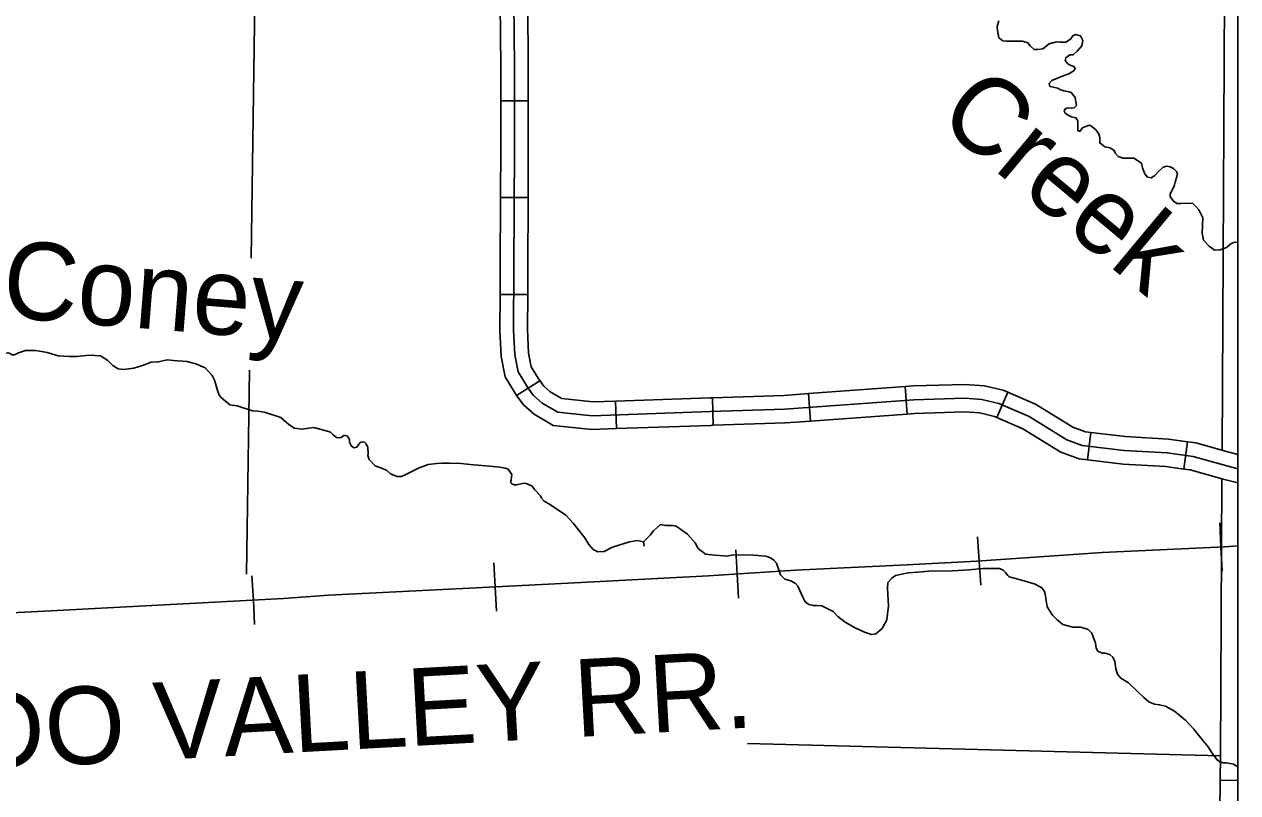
# Model space of a CAD drawing. Extents: x 8749 to 11879, y 13275 to 15339.
# Drawn here: x 10827.5 to 10959.7, y 14275.3 to 14359.1 of the extents above; entities that cross this region are included whole.
import ezdxf

# ---------------------------------------------------------------- set-up
doc = ezdxf.new("R2010")
doc.units = 0
for name, color, linetype in [('Level 31', 7, 'Continuous'), ('Level 32', 7, 'Continuous'), ('Level 35', 7, 'Continuous'), ('Level 4', 7, 'Continuous'), ('Level 40', 7, 'Continuous'), ('Level 5', 7, 'Continuous'), ('R_Draft', 7, 'Continuous')]:
    doc.layers.add(name, color=color, linetype=linetype)

msp = doc.modelspace()

# ---------------------------------------------------------------- linework, layer by layer
at = {"layer": 'Level 31'}
for points in [[(10881.44, 14382.4), (10881.09, 14375.29), (10880.86, 14361.44), (10880.91, 14354.46), (10880.91, 14345.65)], [(10880.91, 14345.65), (10880.86, 14332.43), (10880.82, 14325.76), (10880.95, 14323.05), (10881.31, 14321.18), (10882.42, 14319.41), (10883, 14318.6), (10883.93, 14317.78), (10885.62, 14316.8), (10889.39, 14316.4), (10902.27, 14316.85), (10910.36, 14317.12), (10924.44, 14318.14), (10929.99, 14318.32), (10931.85, 14318.18), (10933.67, 14317.74), (10937.01, 14316.32), (10941.09, 14313.78), (10942.78, 14313.16), (10947.35, 14312.62), (10952.02, 14312.36), (10954.86, 14311.96), (10958.52, 14310.93), (10959.72, 14310.62)], [(10923.65, 14300.13), (10931.3, 14300.54), (10944.95, 14301.48), (10958.32, 14302.12), (10959.72, 14302.2)], [(10745.11, 14290.62), (10758.52, 14291.3), (10770.32, 14291.88), (10786.12, 14292.74), (10797.56, 14293.42), (10807.72, 14293.91), (10816.51, 14294.45), (10829.7, 14295.08), (10847.57, 14296.03), (10855.76, 14296.48), (10860.67, 14296.84), (10876.02, 14297.61), (10886.78, 14298.15), (10902.05, 14298.96), (10911.55, 14299.55), (10923.65, 14300.13)]]:
    msp.add_lwpolyline(points, dxfattribs=at)
at = {"layer": 'Level 32'}
for p, q in [((10879.41, 14350.73), (10882.41, 14350.73)), ((10879.39, 14340.18), (10882.39, 14340.17)), ((10879.35, 14329.62), (10882.35, 14329.6)), ((10881.15, 14318.61), (10883.69, 14320.2)), ((10923.71, 14316.58), (10923.5, 14319.57)), ((10902.57, 14315.36), (10902.48, 14318.36)), ((10913.18, 14315.82), (10912.96, 14318.81)), ((10933.48, 14316.19), (10934.66, 14318.95)), ((10892.02, 14314.99), (10891.92, 14317.99)), ((10943.36, 14311.58), (10943.71, 14314.56)), ((10953.83, 14310.59), (10954.25, 14313.56))]:
    msp.add_line(p, q, dxfattribs=at)
for points in [[(10879.37, 14361.28), (10879.41, 14354.45), (10879.41, 14350.73)], [(10882.36, 14361.3), (10882.41, 14354.46), (10882.41, 14350.73)], [(10879.41, 14350.73), (10879.41, 14345.66), (10879.39, 14340.18)], [(10882.41, 14350.73), (10882.41, 14345.65), (10882.39, 14340.17)], [(10879.39, 14340.18), (10879.36, 14332.44), (10879.35, 14329.62)], [(10882.39, 14340.17), (10882.36, 14332.42), (10882.35, 14329.6)], [(10879.35, 14329.62), (10879.32, 14325.73), (10879.46, 14322.87), (10879.89, 14320.63), (10881.15, 14318.61)], [(10882.35, 14329.6), (10882.32, 14325.79), (10882.45, 14323.23), (10882.73, 14321.74), (10883.69, 14320.2)], [(10883.67, 14320.24), (10884.11, 14319.62), (10884.81, 14319.01), (10886.09, 14318.26), (10889.45, 14317.91), (10891.92, 14317.99)], [(10912.96, 14318.81), (10923.5, 14319.57)], [(10923.5, 14319.57), (10924.36, 14319.64), (10930.02, 14319.82), (10932.09, 14319.67), (10934.15, 14319.17), (10934.66, 14318.95)], [(10881.14, 14318.62), (10881.17, 14318.57), (10881.88, 14317.59), (10883.05, 14316.56), (10885.14, 14315.35), (10889.34, 14314.9), (10892.02, 14314.99)], [(10891.92, 14317.99), (10902.22, 14318.35), (10902.48, 14318.36)], [(10902.48, 14318.36), (10910.28, 14318.61), (10912.96, 14318.81)], [(10934.66, 14318.95), (10937.7, 14317.65), (10941.75, 14315.14), (10943.13, 14314.63), (10943.71, 14314.56)], [(10923.71, 14316.58), (10924.51, 14316.64), (10929.96, 14316.81), (10931.62, 14316.7), (10933.2, 14316.31), (10933.48, 14316.19)], [(10902.57, 14315.36), (10910.44, 14315.62), (10913.18, 14315.82)], [(10913.18, 14315.82), (10923.71, 14316.58)], [(10933.48, 14316.19), (10936.31, 14314.98), (10940.43, 14312.43), (10942.43, 14311.69), (10943.36, 14311.58)], [(10892.02, 14314.99), (10902.32, 14315.35), (10902.57, 14315.36)], [(10943.71, 14314.56), (10947.48, 14314.12), (10952.17, 14313.85), (10954.25, 14313.56)], [(10954.25, 14313.56), (10955.17, 14313.43), (10958.91, 14312.38), (10959.72, 14312.17)], [(10943.36, 14311.58), (10947.23, 14311.13), (10951.87, 14310.86), (10953.83, 14310.59)], [(10953.83, 14310.59), (10954.55, 14310.49), (10958.13, 14309.48), (10959.72, 14309.08)]]:
    msp.add_lwpolyline(points, dxfattribs=at)
at = {"layer": 'Level 35'}
for points in [[(10934.13, 14357.26), (10933.7, 14357.6), (10933.55, 14358.38), (10933.5, 14358.81), (10933.7, 14359.44)], [(10941.78, 14355.75), (10942.21, 14356.12), (10942.72, 14356.73), (10942.84, 14357.31), (10942.57, 14357.79), (10942.04, 14357.94), (10941.76, 14357.81), (10941.48, 14357.43), (10941, 14357.11), (10940.32, 14357.13), (10939.97, 14357.16)], [(10939.97, 14357.16), (10939.19, 14356.95), (10938.49, 14356.4), (10937.93, 14356.3), (10937.53, 14356.32), (10937.12, 14356.73), (10936.85, 14357.06), (10936.27, 14357.23), (10935.11, 14357.21), (10934.55, 14357.21), (10934.13, 14357.26)], [(10940.12, 14352.1), (10939.29, 14352.3), (10939.22, 14352.4), (10939.17, 14352.62), (10939.47, 14352.95), (10940.7, 14353.46), (10941.31, 14353.66), (10941.91, 14354.04), (10942.01, 14354.26), (10941.86, 14354.47), (10941.46, 14354.62), (10941.21, 14354.77), (10940.9, 14355.12), (10940.98, 14355.42), (10941.41, 14355.73), (10941.78, 14355.75)], [(10941.6, 14348.98), (10941.16, 14349.2), (10940.9, 14349.38), (10940.8, 14349.6), (10940.88, 14349.8), (10941.16, 14349.96), (10941.61, 14349.91), (10941.89, 14349.96), (10942.16, 14350.23), (10942.01, 14351.07), (10941.58, 14351.62), (10941.21, 14351.75), (10940.78, 14351.82), (10940.35, 14351.97), (10940.12, 14352.1)], [(10949.24, 14343.92), (10948.4, 14344.47), (10947.62, 14344.49), (10947.25, 14344.49), (10946.69, 14344.64), (10946.41, 14344.97), (10946.26, 14345.32), (10945.83, 14345.6), (10945.23, 14345.7), (10944.68, 14346.13), (10944.7, 14346.71), (10944.6, 14347.14), (10944.22, 14347.59), (10943.67, 14348.02), (10943.42, 14348.05), (10942.81, 14347.77), (10942.53, 14347.39), (10942.28, 14347.49), (10942.31, 14348), (10942.31, 14348.53), (10942.08, 14348.88), (10941.6, 14348.98)], [(10957.8, 14334.47), (10957.2, 14334.46), (10956.59, 14334.89), (10955.99, 14335.54), (10955.86, 14336.3), (10955.91, 14337.96), (10955.48, 14338.85), (10955.18, 14339.18), (10954.83, 14339.53), (10954.05, 14339.58), (10953.54, 14339.53), (10953.09, 14339.53), (10952.69, 14339.83), (10952.36, 14340.31), (10952.34, 14340.59), (10952.56, 14340.97), (10952.81, 14341.44), (10952.84, 14341.57), (10952.91, 14341.87), (10953.14, 14342.73), (10953.04, 14343.03), (10952.71, 14343.34), (10952.34, 14343.54), (10951.98, 14343.59), (10951.58, 14343.49), (10951.1, 14343.03), (10950.67, 14342.58), (10950.27, 14342.33), (10949.89, 14342.4), (10949.59, 14342.76), (10949.34, 14343.41), (10949.24, 14343.92)], [(10957.8, 14334.47), (10958.48, 14334.75), (10959, 14335.18), (10959.41, 14335.31), (10959.72, 14335.29)], [(10839.45, 14321.58), (10838.29, 14321.43), (10837.74, 14321.5), (10837.14, 14321.86), (10836.61, 14322.41), (10835.8, 14322.92), (10834.62, 14322.99), (10833.26, 14322.87), (10832.42, 14322.87), (10831.19, 14322.94), (10829.98, 14323.29), (10828.75, 14323.52), (10827.64, 14323.52), (10826.88, 14323.24), (10826.43, 14323.04), (10826.13, 14323.04), (10825.97, 14323.17), (10825.7, 14323.24), (10825.07, 14323.19), (10824.76, 14322.97)], [(10847.99, 14320.79), (10847.21, 14321.63), (10846.2, 14322.06), (10845.22, 14322.31), (10843.75, 14322.41), (10843.07, 14322.49), (10842.14, 14322.26), (10841.31, 14322.24), (10840.38, 14321.88), (10839.45, 14321.58)], [(10860.63, 14314.69), (10859.05, 14315.11), (10857.69, 14314.93), (10856.96, 14315.04), (10856.33, 14315.46), (10855.45, 14316.22), (10853.68, 14316.8), (10852.9, 14316.88), (10852.35, 14316.93), (10850.68, 14317.46), (10849.9, 14317.58), (10849.42, 14317.99), (10848.99, 14318.36), (10848.72, 14318.64), (10848.59, 14319.05), (10848.24, 14320.26), (10847.99, 14320.79)], [(10865.08, 14311.61), (10864.95, 14312.05), (10864.96, 14312.24), (10864.92, 14312.95), (10864.74, 14313.35), (10864.57, 14313.51), (10864.37, 14313.55), (10864.11, 14313.48), (10863.87, 14313.18), (10863.72, 14312.98), (10863.44, 14312.89), (10863.16, 14313.08), (10862.95, 14313.51), (10862.92, 14313.86), (10862.67, 14314.2), (10862.48, 14314.25), (10862.33, 14314.24), (10862.04, 14314.01), (10861.83, 14313.98), (10861.52, 14314.01), (10861.16, 14314.3), (10860.87, 14314.59), (10860.63, 14314.69)], [(10879.33, 14310.78), (10877.83, 14310.94), (10876.43, 14311.03), (10875.05, 14311.18), (10873.86, 14311.21), (10873.03, 14311.21), (10872.44, 14311.19), (10871.5, 14311.08), (10870.46, 14310.69), (10868.93, 14309.93), (10868.59, 14309.77), (10868.09, 14309.77), (10867.41, 14310.05), (10866.95, 14310.46), (10866.44, 14310.68), (10865.73, 14310.93), (10865.08, 14311.61)], [(10884.84, 14306.68), (10884.14, 14307.08), (10883.87, 14307.41), (10883.74, 14307.66), (10883.09, 14308.37), (10882.85, 14308.72), (10882.31, 14308.99), (10882.02, 14309.03), (10881.62, 14308.96), (10881.15, 14308.86), (10880.89, 14308.87), (10880.62, 14308.96), (10880.52, 14309.09), (10880.51, 14309.32), (10880.55, 14309.4), (10880.61, 14310.01), (10880.42, 14310.31), (10880.21, 14310.56), (10879.91, 14310.7), (10879.33, 14310.78)], [(10894.97, 14302.65), (10894.3, 14302.79), (10893.43, 14302.64), (10891.59, 14302.07), (10890.69, 14301.61), (10889.98, 14301.57), (10889.49, 14301.82), (10889.02, 14302.38), (10888.57, 14303.08), (10887.35, 14304.65), (10886.49, 14305.57), (10884.84, 14306.68)], [(10904.76, 14301.22), (10904.06, 14301.09), (10903.71, 14301.14), (10902.73, 14301.19), (10901.72, 14301.32), (10900.94, 14301.92), (10900.59, 14302.53), (10899.75, 14303.48), (10899.15, 14303.91), (10898.52, 14304.37), (10898.17, 14304.44), (10897.41, 14304.44), (10896.84, 14304.54), (10896.46, 14304.22), (10896.05, 14303.85), (10895.68, 14303.37), (10894.97, 14302.65), (10895.04, 14302.17)], [(10914.41, 14295.69), (10913.81, 14295.72), (10913.45, 14295.72), (10913, 14295.82), (10912.6, 14296.12), (10912.32, 14296.63), (10911.79, 14297.81), (10911.51, 14298.14), (10911.03, 14298.42), (10910.38, 14298.57), (10909.9, 14299.05), (10909.45, 14300.33), (10909.19, 14300.64), (10908.82, 14300.91), (10908.29, 14301.09), (10906.98, 14301.19), (10904.76, 14301.22)], [(10947.81, 14287.28), (10946.98, 14287.78), (10946.63, 14288.24), (10946.42, 14288.82), (10946.32, 14289.6), (10946.12, 14290.08), (10945.79, 14290.38), (10945.26, 14290.51), (10944.94, 14290.53), (10944.48, 14290.73), (10944.31, 14291.06), (10944.23, 14291.62), (10943.83, 14292.68), (10943.43, 14293.1), (10942.62, 14293.36), (10941.74, 14293.36), (10940.65, 14293.63), (10940.05, 14294.14), (10939.52, 14294.67), (10938.94, 14295.55), (10938.71, 14297.17), (10938.36, 14297.63), (10937.66, 14298.04), (10936.04, 14298.52), (10934.81, 14298.84), (10934.68, 14299), (10934.43, 14299.32), (10934.15, 14299.58), (10933.75, 14299.75), (10932.87, 14299.75), (10931.96, 14299.75), (10930.45, 14299.6), (10928.64, 14299.5)], [(10928.64, 14299.5), (10926.07, 14299.45), (10924.86, 14299.35), (10923.8, 14299.27), (10922.42, 14299), (10922.04, 14298.69), (10921.59, 14298.21), (10921.54, 14297.58), (10921.66, 14295.67), (10921.49, 14294.15), (10920.98, 14293.22), (10920.3, 14292.62), (10919.82, 14292.57), (10919.04, 14292.79), (10918.03, 14293.27), (10916.95, 14293.88), (10916.14, 14294.51), (10915.64, 14295.06), (10914.41, 14295.69)], [(10958.18, 14278.57), (10957.76, 14278.66), (10957.43, 14278.91), (10956.93, 14279.62), (10956.5, 14280.3), (10955.79, 14281.13), (10954.93, 14282.24), (10954.08, 14283.18), (10952.84, 14284.21), (10951.86, 14284.74), (10951.21, 14284.89), (10950.65, 14284.97), (10950.05, 14285.22), (10949.44, 14285.72), (10948.84, 14286.32), (10947.81, 14287.28)], [(10959.72, 14278.14), (10959.26, 14278.42), (10958.48, 14278.55), (10958.18, 14278.57)]]:
    msp.add_lwpolyline(points, dxfattribs=at)
at = {"layer": 'Level 4'}
for points in [[(10959.06, 14413.02), (10958.4, 14386.56), (10958.38, 14383.3), (10958.02, 14312.63)], [(10958, 14309.51), (10957.85, 14279.31), (10957.82, 14276.65), (10956.82, 14183.21)]]:
    msp.add_lwpolyline(points, dxfattribs=at)
at = {"layer": 'Level 40'}
for p, q in [((10957.89, 14302.09), (10957.77, 14304.73)), ((10931.54, 14300.55), (10931.36, 14303.19)), ((10905.18, 14299.15), (10905.02, 14301.79)), ((10957.89, 14302.09), (10958.02, 14299.46)), ((10878.82, 14297.75), (10878.68, 14300.38)), ((10931.54, 14300.55), (10931.72, 14297.92)), ((10852.46, 14296.3), (10852.31, 14298.93)), ((10905.18, 14299.15), (10905.34, 14296.52)), ((10878.82, 14297.75), (10878.95, 14295.11)), ((10852.46, 14296.3), (10852.6, 14293.66))]:
    msp.add_line(p, q, dxfattribs=at)
msp.add_lwpolyline([(10721.25, 14289.28), (10735.4, 14290.14), (10745.11, 14290.62), (10758.52, 14291.3), (10770.32, 14291.88), (10786.12, 14292.74), (10797.56, 14293.42), (10807.72, 14293.91), (10816.51, 14294.45), (10829.7, 14295.08), (10847.57, 14296.03), (10855.76, 14296.48), (10860.67, 14296.84), (10876.02, 14297.61), (10886.78, 14298.15), (10902.05, 14298.96), (10911.55, 14299.55), (10923.65, 14300.13), (10931.3, 14300.54), (10944.95, 14301.48), (10958.32, 14302.12), (10959.72, 14302.2)], dxfattribs=at)
at = {"layer": 'Level 5'}
for points in [[(10853.02, 14389.78), (10852.21, 14333.56)], [(10852.03, 14321.37), (10851.71, 14299.12)], [(10906.3, 14280.68), (10957.85, 14279.31)], [(10957.82, 14276.65), (10959.72, 14276.67)]]:
    msp.add_lwpolyline(points, dxfattribs=at)
at = {"layer": 'R_Draft'}
msp.add_lwpolyline([(9678.09, 14456.3), (10959.72, 14456.3), (10959.72, 13439.87), (9678.09, 13439.87)], close=True, dxfattribs=at)

# ---------------------------------------------------------------- texts
at = {"layer": 'Level 35'}
for s, rotation, p in [('Creek', 320.1666, (10926.74, 14348.53)), ('Coney', 355.3848, (10824.93, 14327.17))]:
    msp.add_text(s, height=8.448, rotation=rotation, dxfattribs=at).set_placement(p)
at = {"layer": 'Level 40'}
msp.add_text('CADDO VALLEY RR.', height=8.448, rotation=3.1413, dxfattribs=at).set_placement((10797.97, 14276.45))

doc.saveas('drawing.dxf')
